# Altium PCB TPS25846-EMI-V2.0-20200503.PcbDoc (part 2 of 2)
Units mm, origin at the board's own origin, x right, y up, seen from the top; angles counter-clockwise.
Board outline 35.01 x 50.01 mm, 4 copper layers (Top Layer, Signal Layer 1, Signal Layer 2, Bottom Layer), stack 2.155 mm thick; 63 components, 30 nets, 189 pads, 82 vias.
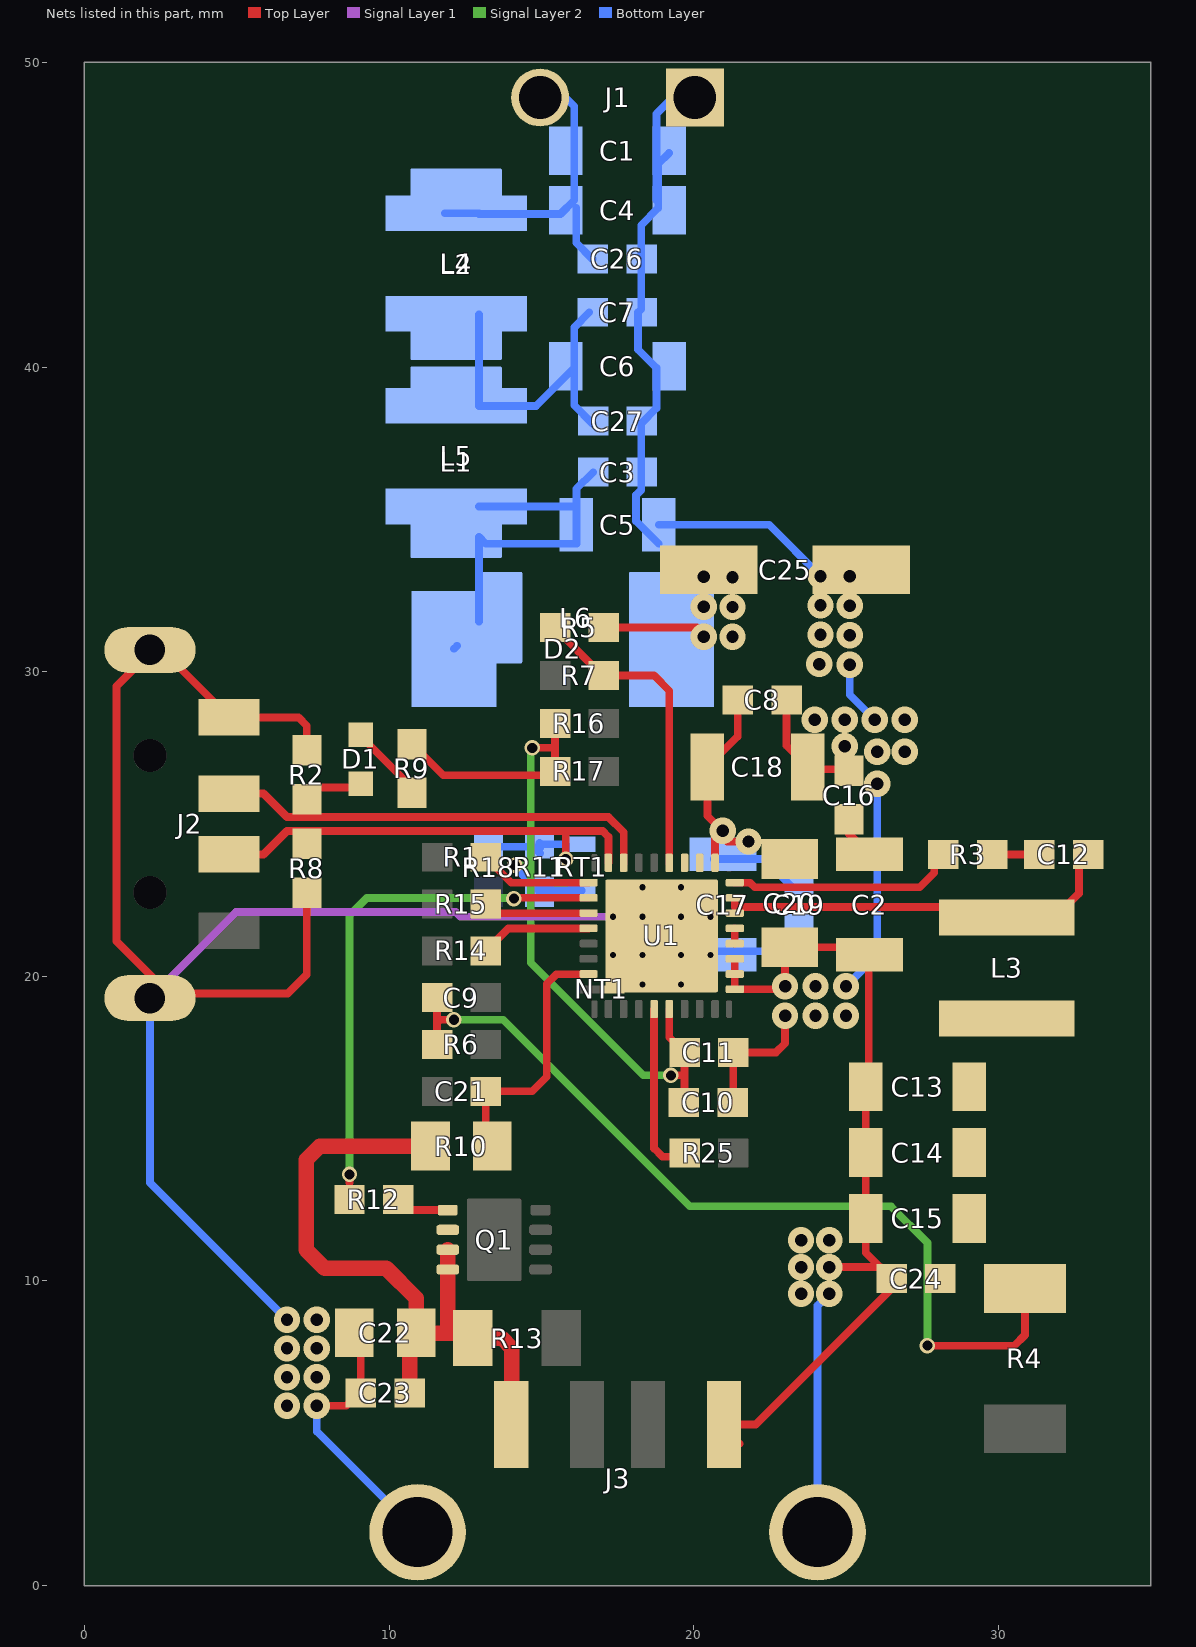
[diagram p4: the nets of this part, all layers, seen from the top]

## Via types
v1: diameter 0.864, hole 0.406, Top Layer to Bottom Layer, 56 vias
v2: diameter 0.508, hole 0.33, Top Layer to Bottom Layer, 14 vias
v3: diameter 0.5, hole 0.2, Top Layer to Bottom Layer, 12 vias

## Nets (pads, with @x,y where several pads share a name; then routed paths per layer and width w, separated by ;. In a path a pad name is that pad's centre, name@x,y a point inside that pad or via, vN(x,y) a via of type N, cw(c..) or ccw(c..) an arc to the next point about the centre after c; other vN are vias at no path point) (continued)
DATA_OUT_N: J2.2 R8.2 R11.1 R18.2 RT1.1 U1.8 | length 17.9
  Top Layer w0.254: J2.2@4.75,24 5.877,24 6.648,24.771 15.85,24.771 ; v2(15.8,23.85) 15.8,24.721 15.85,24.771 ; U1.8@17.2,23.725 17.2,24.582 17.01,24.771 15.85,24.771
  Bottom Layer w0.254: R18.2@13.239,24.25 14.74,24.25 R11.1@14.953,24.037 ; R11.1@14.915,24.25 R11.1@14.953,24.212 ; R11.1@14.94,24.375 14.978,24.337 15.8,24.337 v2(15.8,23.85)
DATA_OUT_P: D1.1 J2.3 R2.2 U1.7 | length 16.4
  Top Layer w0.254: J2.3@4.75,26 5.877,26 6.648,25.229 17.2,25.229 17.7,24.728 U1.7@17.7,23.725 U1.7@17.7,23.72 ; R2.2@7.3,25.816 7.684,26.2 D1.1@9.075,26.2
IN: C2.1 C8.1 C16.1 C17.1 C18.1 C19.1 C20.1 C25.1 D2.1 L6.2 R5.2 U1.1 U1.2 U1.3 | length 14.6
  Top Layer w0.254: R5.2@17.05,31.45 20.112,31.45 20.325,31.237 v1(20.325,31.15) ; U1.1@20.7,23.725 20.7,24.725 20.75,24.775 v1@20.85,24.675 ; v1(20.95,24.775) 20.45,25.275 C18.1@20.45,26.875 21.45,27.875 C8.1@21.45,29.075 ; v1@21.1,24.425 v1(21.8,24.425) ; C16.1@25.1,25.15 25.1,24.675 C2.1@25.775,24
  Bottom Layer w0.254: C17.1@20.659,23.85 22.3,23.85 C19.1@23.15,23
  other v1: 21.275,31.15 20.325,32.132 21.275,32.125 21.275,33.1 20.325,33.114
LS_GD: R12.1 U1.10 | length 16.9
  Top Layer w0.254: 8.7,13.225 v2(8.7,13.5) ; v2@14.055,22.575 U1.10@16.55,22.575
  Signal Layer 2 w0.254: v2(8.7,13.5) 8.7,22 9.27,22.57 v2@14.05,22.57
  other v2: 14.1,22.55
NetC3_1: C3.1 C5.1 D2.2 L1.2 L5.2 L6.1 | length 12
  Bottom Layer w0.254: D2.2@12.131,30.75 D2.2@12.231,30.85 ; D2.2@12.95,31.649 12.95,34.425 13.175,34.2 16.15,34.2 C5.1@16.15,34.825 C5.1@16.15,35.441 ; L5.2@12.95,35.424 16.133,35.424 C5.1@16.15,35.441 ; C3.1@16.7,36.55 16.15,36 C5.1@16.15,35.441
NetC6_1: C6.1 C7.1 C27.1 L1.1 L2.2 L4.2 L5.1 | length 10.7
  Bottom Layer w0.254: L4.2@12.95,41.724 12.95,40.925 12.95,39.325 12.95,38.726 14.826,38.726 C6.1@16.075,39.975 ; C7.1@16.575,41.8 16.075,41.3 C6.1@16.075,39.975 ; C27.1@16.675,38.15 16.075,38.75 C6.1@16.075,39.975
NetC9_2: C9.2 C13.1 C14.1 C15.1 C24.1 L3.2 R4.1 R6.2 | length 29.1
  Top Layer w0.254: C9.2@11.575,19.299 11.575,18.475 ; R6.2@11.662,17.849 R6.2@11.575,17.762 11.575,18.475 ; v2(12.125,18.574) 11.674,18.574 11.575,18.475 ; v2(27.675,7.875) 30.525,7.875 30.875,8.225 R4.1@30.875,9.75
  Signal Layer 2 w0.254: v2(12.125,18.574) 13.75,18.574 19.873,12.45 26.475,12.45 27.675,11.25 v2(27.675,7.875)
NetC12_1: C12.1 R3.2 | length 1.6
  Top Layer w0.254: R3.2@29.5,24 31.025,24 C12.1@31.05,24.025
NetC21_1: C21.1 R10.1 U1.15 | length 8.6
  Top Layer w0.254: R10.1@13.391,14.425 13.175,14.641 C21.1@13.175,16.225 14.7,16.225 15.175,16.7 15.175,19.75 15.495,20.07 U1.15@16.55,20.07
NetC22_1: C22.1 C23.1 J3.1 Q1.6 Q1.7 Q1.8 R10.2 R13.1 | length 23.4
  Top Layer w0.508: C23.1@10.672,6.375 10.672,8.059 C22.1@10.888,8.275 ; R10.2@11.359,14.425 7.725,14.425 7.275,13.975 7.275,11.022 7.881,10.416 9.906,10.416 10.888,9.434 C22.1@10.888,8.275 ; Q1.7@11.925,11.025 Q1.8@11.925,10.375 11.925,8.325 11.975,8.275 ; R13.1@12.71,8.385 R13.1@12.6,8.275 ; J3.1@14.01,5.285 14.025,5.3 14.025,7.8 13.7,8.125 R13.1@12.75,8.125 R13.1@12.6,8.275 ; C22.1@10.888,8.275 11.975,8.275 ; 11.975,8.275 R13.1@12.6,8.275
NetD1_2: D1.2 R9.1 | length 2.6
  Top Layer w0.254: D1.2@9.075,27.925 9.075,27.875 10.747,26.203 R9.1@10.747,26.025
NetQ1_5: Q1.5 R12.2 | length 1.7
  Top Layer w0.254: R12.2@10.3,12.525 10.5,12.325 Q1.5@11.925,12.325
NetR1_2: R1.2 U1.9 | length 3.7
  Top Layer w0.254: R1.2@13.175,23.907 14.012,23.07 U1.9@16.55,23.07
NetR3_1: R3.1 U1.32 | length 7.4
  Top Layer w0.254: U1.32@21.35,23.075 21.85,23.075 22,22.925 27.425,22.925 27.9,23.4 R3.1@27.9,24
NetR5_1: R5.1 R7.2 U1.4 | length 10.2
  Top Layer w0.254: R5.1@15.45,31.55 15.45,31.425 R7.2@16.9,29.975 ; R7.2@17.05,29.874 18.701,29.874 19.2,29.375 U1.4@19.2,23.72
NetR14_2: R14.2 U1.12 | length 3.7
  Top Layer w0.254: R14.2@13.175,20.834 13.911,21.57 U1.12@16.55,21.57
NetR15_1: R15.1 U1.11 | length 3.4
  Top Layer w0.254: R15.1@13.175,22.05 13.195,22.07 U1.11@16.55,22.07
NetR25_2: R25.2 U1.20 | length 5.7
  Top Layer w0.254: U1.20@18.7,18.92 18.7,14.35 18.975,14.075 19.575,14.075 R25.2@19.7,14.2
PGND: C1.2 C2.2 C3.2 C4.2 C5.2 C6.2 C7.2 C8.2 C10.2 C11.2 C13.2 C14.2 C15.2 C16.2 C17.2 C18.2 C19.2 C20.2 C22.2 C23.2 C24.2 C25.2 C26.2 C27.2 J1.1 J2.4 J2.5 J2.6 J3.4 J3.5 J3.6 NT1.1 R2.1 R8.1 U1.25 U1.26 U1.27 U1.33@18.95,21.325 | length 148.1
  Top Layer w0.254: J2.6@2.15,30.715 J2.6@2.24,30.715 ; R8.1@7.3,22.75 7.3,20.06 6.675,19.435 2.765,19.435 1.05,21.15 1.05,29.525 J2.6@2.24,30.715 ; R2.1@7.3,27.416 7.3,28.225 7.025,28.5 J2.4@4.75,28.5 2.535,30.715 J2.6@2.24,30.715 ; v1(7.625,5.9) 8.597,5.9 9.072,6.375 9.072,8.059 C22.2@8.856,8.275 ; U1.33@18.95,21.325 19.349,20.926 19.25,20.926 19.25,20.553 19.443,20.36 19.58,20.36 v3(19.58,19.725) ; J3.4@20.99,5.285 J3.4@21.29,5.285 ; C10.2@21.275,15.858 21.3,15.883 C11.2@21.3,17.5 22.7,17.5 23,17.8 v1(23,18.7) ; U1.27@21.35,20.575 U1.26@21.35,20.075 U1.25@21.35,19.575 22.9,19.575 v1(23,19.675) 23,20.8 C20.2@23.15,20.95 25.65,20.95 C2.2@25.75,20.85 ; J3.4@21.515,4.65 21.29,4.875 J3.4@21.29,5.285 ; C8.2@23.05,29.075 23.05,27.575 C18.2@23.75,26.875 23.675,26.8 25.05,26.8 C16.2@25.1,26.75 ; v1(24.45,10.453) C24.2@26.122,10.453 ; C2.2@25.75,20.7 25.75,16.45 25.65,16.35 C14.2@25.65,14.212 25.65,10.925 C24.2@26.122,10.453 ; J3.4@21.29,5.285 22.035,5.285 26.5,9.75 C24.2@26.5,10.075 C24.2@26.122,10.453
  Signal Layer 1 w0.254: J2.5@2.15,19.285 4.972,22.107 12.189,22.107 12.342,21.955 v3(17.35,21.955)
  Bottom Layer w0.254: J2.5@2.15,19.285 2.15,13.223 v1(6.648,8.725) ; v1(7.625,5.9) 7.625,5.06 J3.5@10.935,1.75 ; C4.2@18.775,45.475 18.775,48.31 J1.1@20.09,49.625 ; C5.2@18.85,34.2 18.109,34.941 18.109,35.8 18.275,35.966 18.275,38.15 18.775,38.65 18.775,39.975 18.175,40.575 18.175,41.8 18.275,41.9 18.275,44.66 18.84,45.225 18.84,46.675 C1.2@19.19,47.025 ; C5.2@18.85,34.825 22.476,34.825 v1(24.161,33.139) ; v3(20.55,20.695) 20.68,20.825 22.575,20.825 C19.2@23.15,21.4 ; J3.6@24.065,1.75 24.065,9.19 v1(24.45,9.575) ; v1(25,19.675) 26.025,20.7 v1(26.025,26.325) ; v1(25.125,30.225) 25.125,29.242 v1(25.942,28.425)
  other v1: 6.648,5.9 6.648,6.842 7.625,6.842 6.648,7.783 7.625,7.783 7.625,8.725 23.525,9.575 23.525,10.453 23.525,11.331 24.45,11.331 24,18.7 25,18.7 24,19.675 26.025,27.375 26.925,27.375 24.958,27.55 23.975,28.425 24.958,28.425 26.925,28.425 24.125,30.25 25.125,31.196 24.161,31.213 25.125,32.168 24.161,32.176 25.125,33.139
  other v3: 18.32,19.725 17.35,20.695 18.32,20.695 19.58,20.695 18.32,21.955 19.58,21.955 20.55,21.955 18.32,22.925 19.58,22.925
SW: C12.2 L3.1 U1.28 U1.29 U1.30 U1.31 | length 13.9
  Top Layer w0.254: U1.28@21.35,21.07 U1.28@21.35,21.075 U1.29@21.35,21.57 ; U1.31@21.35,22.57 21.35,22.275 29.855,22.275 L3.1@30.2,21.93 ; L3.1@30.275,21.93 31.86,21.93 32.65,22.72 C12.2@32.65,24.025
  Top Layer w0.508: L3.1@30.2,21.93 L3.1@30.2,22.03
VBAT: C1.1 C4.1 C26.1 J1.2 L2.1 L4.1 | length 10.9
  Bottom Layer w0.254: L4.1@11.825,45.05 L4.1@12.95,45.05 ; L4.1@12.95,45.026 15.626,45.026 16.075,45.475 16.075,48.56 J1.2@15.01,49.625 ; C4.1@16.14,45.225 16.14,44.085 C26.1@16.675,43.55
VCC: C10.1 C11.1 R9.2 R11.2 R16.2 R17.2 RT1.2 U1.21 | length 27.6
  Top Layer w0.254: R9.2@10.747,27.625 11.775,26.597 15.322,26.597 R17.2@15.45,26.725 15.45,27.5 ; v2(14.7,27.5) 15.45,27.5 ; R16.2@15.45,28.301 15.45,27.5 ; R16.2@15.675,28.301 R16.2@15.675,28.325 ; U1.21@19.2,18.92 19.2,18 C11.1@19.7,17.5 19.7,16.75 ; v2(19.25,16.75) 19.7,16.75 ; C10.1@19.675,15.858 19.7,15.883 19.7,16.75
  Signal Layer 2 w0.254: v2(14.125,23.65) 14.65,23.65 ; v2(14.7,27.5) 14.65,27.45 14.65,23.65 ; v2(19.25,16.75) 18.35,16.75 14.65,20.45 14.65,23.65
  Bottom Layer w0.254: v2(14.125,23.65) 14.125,23.59 R11.2@14.94,22.775 14.978,22.813 RT1.2@16.325,22.813 ; R11.2@14.915,22.65 R11.2@14.94,22.65
pads on no net: J2.1 J2.7 J2.8 Q1.4 Q1.9 U1.19 U1.22 U1.23 U1.33@17.69,20.065 U1.33@17.69,21.325 U1.33@17.69,22.585 U1.33@18.95,20.065 U1.33@18.95,21.325 U1.33@18.95,22.585 U1.33@20.21,20.065 U1.33@20.21,21.325 U1.33@20.21,22.585 U1.A1 U1.A2 U1.A3 U1.A4
copper on no net: | length 5.9
  Top Layer w0.254: 17.347,19.57 17.347,19.717 ; 18.32,20.69 18.32,21.95 19.58,21.95 19.58,22.92 18.32,22.92 ; 19.58,20.69 20.55,20.69

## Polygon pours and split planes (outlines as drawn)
IN on Top Layer "TOP_LAYER_IN_P204" (solid, remove dead copper, pour order 204): 18.145,34.175 21.916,34.175 22.091,34 22.091,30.241 21.825,29.975 19.625,29.975 19.2,30.4 18.1,30.4 17.9,30.6 17.9,33.964
CSN on Top Layer "TOP_LAYER_CSN_P182" (solid, remove dead copper, pour order 182): 15.5,13.6 16.64,13.6 16.75,13.49 16.75,7.065 16.635,6.95 14.925,6.95 14.775,7.1 14.775,8.94 14.525,9.19 14.525,11.85 14.65,11.975 15.29,11.975 15.415,12.1 15.415,13.475
NetC22_1 on Top Layer "TOP_LAYER_NETC22_1_P180" (solid, remove dead copper, pour order 180): 10.2,11.759 10.316,11.875 12.215,11.875 12.3,11.79 12.3,9.214 12.5,9.1 12.575,9.1 14.262,9.1 14.575,8.787 14.575,3.71 14.465,3.6 10.369,3.6 10.2,3.78 10.2,4.075
SW on Top Layer "TOP_LAYER_SW_P176" (solid, remove dead copper, pour order 176): 21.05,22.7 21.649,22.7 21.799,22.55 27.745,22.55 28.21,23.015 32.95,23.015 33.115,22.85 33.115,20.915 32.987,20.787 28.388,20.787 27.675,21.5 24.625,21.5 24.275,21.85 22.075,21.85 21.9,21.675 21.9,21.1 21.734,20.934 21.05,20.934
IN on Top Layer "TOP_LAYER_IN_P174" (solid, remove dead copper, pour order 174): 19.806,33.85 21.887,33.85 22.091,33.645 22.091,25.984 22.55,25.525 26.7,25.525 26.95,25.275 26.95,23.409 26.666,23.125 22.25,23.125 21.3,24.075 21.275,24.1 21.05,24.1 20.965,24.015 20.965,23.465 20.895,23.395 19.619,23.395 19.619,33.605
no net on Top Layer "TOP_LAYER_NONET_P172" (solid, remove dead copper, pour order 172): 19.434,33.8
PGND on Top Layer "TOP_LAYER_PGND_P170" (solid, remove dead copper, pour order 170): 20.15,20.775 20.235,20.69 21.01,20.69 21.025,20.675 21.025,20.364 20.79,20.129 20.62,20.3 20.2,20.3 20.2,20.65 20.15,20.7
PGND on Top Layer "TOP_LAYER_PGND_P158" (solid, remove dead copper, pour order 158): 1.575,34.125 33.327,34.125 34.15,33.302 34.15,1.133 33.525,0.508 1.425,0.508 0.7,1.233 0.7,33.25
no net on Top Layer "TOP_LAYER_NONET_P156" (solid, remove dead copper, pour order 156): 1.225,33.775
CSN on Top Layer "TOP_LAYER_CSN_P152" (solid, remove dead copper, pour order 152): 26.825,6.475 32.375,6.475 32.745,6.105 32.745,4.295 32.4,3.95 26.85,3.95 26.475,4.325 26.475,6.125
NetC9_2 on Top Layer "TOP_LAYER_NETC9_2_P150" (solid, remove dead copper, pour order 150): 27.575,19.153 28.102,19.525 32.275,19.525 32.6,19.2 32.6,8.95 32.075,8.425 27.971,8.425 27.575,8.98
no net on Top Layer "TOP_LAYER_NONET_P132" (solid, remove dead copper, pour order 132): 21.525,24.872
no net on Top Solder "TOP_LAYER_NONET_P-001" (solid, remove dead copper): -35.968,-41.976
PGND on Signal Layer 2 "SIGNAL_LAYER_2_PGND_P188" (solid, remove dead copper, pour order 188): 1.525,34.175 33.187,34.175 34.1,33.262 34.1,1.183 33.475,0.558 1.375,0.558 0.65,1.283 0.65,33.3
CSN on Signal Layer 2 "SIGNAL_LAYER_2_CSN_P184" (solid, remove dead copper, pour order 184): 14.05,13.7 16.54,13.7 16.9,13.34 16.9,10.825 21.375,6.35 29.625,6.35 29.95,6.025 29.95,4 29.625,3.675 20,3.675 15.15,8.525 13.825,9.85 13.825,13.475
PGND on Signal Layer 1 "SIGNAL_LAYER_1_PGND_P186" (solid, remove dead copper, pour order 186): 1.575,34.125 33.327,34.125 34.15,33.302 34.15,1.133 33.525,0.508 1.425,0.508 0.7,1.233 0.7,33.25
PGND on Bottom Layer "BOTTOM_LAYER_PGND_P202" (solid, remove dead copper, pour order 202): 18.034,49.484 21.991,49.484 22.275,49.2 22.275,38.25 26.775,33.75 29.5,31.025 29.5,30.6 28.325,29.425 23.418,29.425 22.95,29.893 22.95,33.518 22.518,33.95 18.05,33.95 17.75,34.25 17.75,49.2
IN on Bottom Layer "BOTTOM_LAYER_IN_P200" (solid, remove dead copper, pour order 200): 17.85,33.425 18.075,33.65 22.45,33.65 22.625,33.475 22.625,24.425 23.3,23.75 23.8,23.75 24.065,23.485 24.065,22.64 23.825,22.4 20.8,22.4 17.85,25.35
NetC3_1 on Bottom Layer "BOTTOM_LAYER_NETC3_1_P196" (solid, remove dead copper, pour order 196): 9.35,37.1 17.15,37.1 17.3,36.95 17.3,28.775 17.1,28.575 9.525,28.575 9.2,28.9 9.2,36.675 9.2,36.95
NetC6_1 on Bottom Layer "BOTTOM_LAYER_NETC6_1_P194" (solid, remove dead copper, pour order 194): 9.418,42.45 17.175,42.45 17.35,42.275 17.35,37.825 17.15,37.625 9.45,37.625 9.225,37.85 9.225,42.139
VBAT on Bottom Layer "BOTTOM_LAYER_VBAT_P192" (solid, remove dead copper, pour order 192): 9.829,49.825 16.525,49.825 17.3,49.05 17.3,43.1 17.075,42.875 9.5,42.875 9.225,43.15 9.225,49.267
PGND on Bottom Layer "BOTTOM_LAYER_PGND_P190" (solid, remove dead copper, pour order 190): 1.45,32.625 33.15,32.625 34.15,31.625 34.15,1.133 33.525,0.508 1.425,0.508 0.7,1.233 0.7,31.875

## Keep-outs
Keep-Out Layer:
  text ".Layer_Name" at -65.219,-64.806 h1.52

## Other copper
Top Layer:
  pour cut-out: 32.865,19.181 32.884,20.725 32.605,20.725 32.614,19.181
  pour cut-out: 27.588,19.4 27.609,21.05 27.322,21.05 27.332,19.4
  pour cut-out: 3.726,24.467 3.737,25.325 3.496,25.325 3.501,24.467
  pour cut-out: 8.695,26.671 8.705,27.529 8.464,27.529 8.47,26.671
  pour cut-out: 27.419,6.888 27.44,8.563 27.145,8.562 27.155,6.888
  pour cut-out: 32.831,5.625 32.87,8.694 32.642,8.694 32.66,5.625
  pour cut-out: 14.648,3.45 19.314,3.45 19.314,3.725 14.648,3.725
  pour cut-out: 18.088,13.467 18.946,13.456 18.946,13.698 18.088,13.692
  text ".Layer_Name" at -65.219,-64.806 h1.52
Signal Layer 2:
  pour cut-out: -4.107,-15.263
  pour cut-out: -32.098,-20.595
Bottom Layer:
  pour cut-out: -39.667,-5.687
  text ".Layer_Name" at -65.219,-64.806 h1.52

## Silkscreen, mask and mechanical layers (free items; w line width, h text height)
Top Overlay:
  pour cut-out: -60.476,-31.557
  pour cut-out: -65.87,-32.475
  lines w0.127: -79.675,-35.025 -79.45,-35.25
  text "TPS25846-EMI" at 2.175,36.65 h2 r90
  text "PMP40725" at 32.925,35.775 h2.79 r90
  text ".Layer_Name" at -65.219,-64.806 h1.52
Bottom Overlay:
  text "VIN" at 12.65,48.024 h1.85
  text "GND" at 25.225,48.025 h1.85
  text ".Layer_Name" at -65.219,-64.806 h1.52
Top Paste:
  text ".Layer_Name" at -65.219,-64.806 h1.52
Bottom Paste:
  text ".Layer_Name" at -65.219,-64.806 h1.52
Top Solder:
  rectangle: 12.988,7.15 14.487,9.1
  text ".Layer_Name" at -65.219,-64.806 h1.52
  text ".Layer_Name" at -65.219,-64.806 h1.52
Bottom Solder:
  rectangle: 14.375,30.225 17.5,33.325
  region: 21.225,46.975 21.225,49.875 18.55,49.875 18.55,46.975
  region: 16.375,47.125 16.375,49.875 13.725,49.875 13.725,47.125
  text ".Layer_Name" at -65.219,-64.806 h1.52
Drill Guide:
  text ".Layer_Name" at -65.219,-64.806 h1.52
M1 Board Outline:
  lines w0.01: -39.75,-28.25 -39.725,-28.275 ; 0,0 35,0 35,50 0,50 0,0
  lines w0.254: -82.758,-41.522 -82.25,-43.046 ; -82.758,-14.57 -82.25,-13.046 ; -82.504,-43.046 -81.996,-43.046 ; -82.504,-13.046 -81.996,-13.046 ; -82.25,-33.15 -82.25,-43.046 ; -82.25,-22.942 -82.25,-13.046 ; -81.742,-41.522 -82.25,-43.046 ; -81.742,-14.57 -82.25,-13.046 ; -79.476,-44.69 -79.476,-44.182 ; -77.952,-44.944 -79.476,-44.436 ; -77.952,-43.928 -79.476,-44.436 ; -62.08,-44.436 -79.476,-44.436 ; -51.872,-44.436 -34.476,-44.436 ; -36,-44.944 -34.476,-44.436 ; -36,-43.928 -34.476,-44.436 ; -34.476,-44.69 -34.476,-44.182
  text "30 (mm)" at -81.336,-32.896 h1.52 r90
  text "45 (mm)" at -61.826,-45.35 h1.52
  text ".Layer_Name" at -65.219,-64.806 h1.52
M2 Board Dimensions:
  rectangle: -79.875,-49.985 -76.7,-46.81
  rectangle: -76.7,-53.16 -67.175,-49.985
  lines w0.01: -80.131,-41.674 -80.098,-41.706
  lines w0.178: -79.875,-49.985 -54.475,-49.985 ; -76.7,-53.16 -76.7,-46.81 ; -73.525,-53.16 -73.525,-46.81 ; -67.175,-53.16 -67.175,-46.81 ; -60.825,-53.16 -60.825,-46.81 ; -79.875,-53.16 -54.475,-53.16 -54.475,-46.81 -79.875,-46.81 -79.875,-53.16
  text ".Layer_Name" at -65.219,-64.806 h1.52
M3 3D STEP Top:
  text ".Layer_Name" at -65.219,-64.806 h1.52
M4 3D STEP Bottom:
  text ".Layer_Name" at -65.219,-64.806 h1.52
M5 Assembly Top:
  lines w0.254: -87.292,-66.626 80.348,-66.626 ; -87.292,-61.462 80.399,-61.462 ; -87.292,-56.297 -87.292,-71.791 14.435,-71.791 80.399,-71.791 80.399,-56.297 -87.279,-56.297 -87.279,-71.791 -47.261,-71.791 ; -24.681,-71.791 -24.681,-56.297 ; 7.501,-61.462 7.501,-56.297 ; 28.837,-61.462 28.837,-56.297 ; 44.636,-71.956 44.636,-66.804
  text "COMPONENTS MARKED 'DNP' SHOULD NOT BE POPULATED." at -50.576,-51.09 h1.52
  text "ASSEMBLY VARIANT:" at -50.589,-54.024 h1.52
  text ".VariantName" at -24.274,-54.024 h1.52
  text "PCB VIEWED FROM TOP SIDE" at -85.679,-59.654 h1.52
  text "BOARD #:" at -22.776,-59.654 h1.52
  text ".PRJ_Number" at -8.92,-59.654 h1.52
  text "REV:" at 12.53,-59.654 h1.52
  text ".PCB_Rev" at 19.934,-59.654 h1.52
  text "SVN REV:" at 33.815,-59.654 h1.52
  text ".VersionControl_RevNumber" at 46.668,-59.654 h1.52
  text "TID #:" at -22.776,-64.819 h1.52
  text ".TID" at -8.92,-64.819 h1.52
  text "PLOT NAME =" at -85.679,-70.034 h1.52
  text ".plot_File_Name" at -65.219,-70.034 h1.52
  text "GENERATED    :" at -22.725,-70.034 h1.52
  text ".Print_Date" at -0.64,-70.034 h1.52
  text ".Print_Time" at 17.877,-70.034 h1.52
  text "TEXAS INSTRUMENTS" at 49.995,-70.034 h1.52
M6 Assembly Bottom:
  lines w0.254: -87.304,-61.474 80.386,-61.474 ; -87.254,-66.639 80.386,-66.639 ; -51.541,-71.969 -51.541,-66.817 ; -35.742,-61.474 -35.742,-56.31 ; -14.406,-61.474 -14.406,-56.31 ; 17.775,-71.804 17.775,-56.31 ; 40.356,-71.804 80.374,-71.804 80.374,-56.31 -87.304,-56.31 -87.304,-71.804 -21.341,-71.804 80.386,-71.804 80.386,-56.31
  text "COMPONENTS MARKED 'DNP' SHOULD NOT BE POPULATED." at 75.116,-51.077 h1.52
  text ".VariantName" at 48.598,-54.024 h1.52
  text "ASSEMBLY VARIANT:" at 74.989,-54.024 h1.52
  text ".VersionControl_RevNumber" at -53.573,-59.667 h1.52
  text "SVN REV:" at -40.721,-59.667 h1.52
  text ".PCB_Rev" at -26.84,-59.667 h1.52
  text "REV:" at -19.436,-59.667 h1.52
  text ".PRJ_Number" at 2.015,-59.667 h1.52
  text "BOARD #:" at 15.87,-59.667 h1.52
  text "PCB VIEWED FROM BOTTOM SIDE" at 78.773,-59.667 h1.52
  text ".TID" at 2.015,-64.831 h1.52
  text "TID #:" at 15.87,-64.831 h1.52
  text "TEXAS INSTRUMENTS" at -56.901,-70.047 h1.52
  text ".Print_Time" at -24.782,-70.047 h1.52
  text ".Print_Date" at -6.266,-70.047 h1.52
  text "GENERATED    :" at 15.82,-70.047 h1.52
  text ".plot_File_Name" at 58.314,-70.047 h1.52
  text "PLOT NAME =" at 78.773,-70.047 h1.52
M9 Title Sheet:
  drawing of 57 lines, arcs and shapes, not listed
  text "1" at -61.083,161.127 h1.78
  text "2" at 2.307,161.127 h1.78
  text "3" at 65.536,161.127 h1.78
  text "4" at 129.205,161.127 h1.78
  text "5" at 192.68,161.127 h1.78
  text "6" at 256.307,161.127 h1.78
  text "A" at -90.454,132.095 h1.78
  text "A" at 285.466,132.095 h1.78
  text "B" at -90.454,71.643 h1.78
  text "B" at 285.466,71.643 h1.78
  text "C" at -90.454,11.318 h1.78
  text "C" at 285.466,11.318 h1.78
  text "PROJECT TITLE:" at 208.25,-35.952 h1.14
  text ".PRJ_Title" at 209.52,-39.338 h1.78
  text "DESIGNED FOR:" at 208.25,-43.597 h1.14
  text ".PRJ_Customer" at 209.52,-47.153 h1.78
  text "D" at -90.454,-48.88 h1.78
  text "D" at 285.466,-48.88 h1.78
  text "FILE NAME:" at 208.25,-51.217 h1.14
  text ".PCB_File_Name_No_Path" at 209.52,-54.265 h1.78
  text "Texas Instruments (TI) and/or its licensors do not warrant the accuracy or completeness of this specification" at 82.025,-58.376 h1.14
  text "ENGINEER:" at 208.25,-58.583 h1.14
  text "LAYOUT BY:" at 246.477,-58.583 h1.14
  text "or any information contained therein. TI and/or its licensors do not warrant that this design will meet" at 80.882,-61.237 h1.14
  text ".PRJ_Engineer" at 209.52,-62.52 h1.78
  text ".PCB_Layout" at 247.76,-62.52 h1.78
  text "the specifications, will be suitable for your application or fit for any particular purpose, or will operate in" at 80.882,-64.099 h1.14
  text ".Layer_Name" at -65.219,-64.806 h1.52
  text "ALTIUM DESIGNER VERSION:" at 246.477,-66.457 h1.14
  text "an implementation. TI and/or its licensors do not warrant that the design is production worthy. You should" at 80.882,-66.961 h1.14
  text "completely validate and test your design implementation to confirm the system functionality for your application." at 82.025,-69.822 h1.14
  text ".print_Scale" at 209.52,-69.843 h1.78
  text ".Application_BuildNumber" at 247.76,-69.843 h1.78
  text "1" at -61.083,-75.093 h1.78
  text "2" at 2.307,-75.093 h1.78
  text "3" at 65.536,-75.093 h1.78
  text "4" at 129.205,-75.093 h1.78
  text "5" at 192.68,-75.093 h1.78
  text "6" at 256.307,-75.093 h1.78
M10 Fab Notes:
  drawing of 189 lines, arcs and shapes, not listed
  text "DESIGN INFORMATION" at 234.628,118.447 h1.52
  text "MIN. TRACK WIDTH:" at 218.256,115.091 h1.52
  text "8" at 246.101,115.091 h1.52
  text "MIL" at 250.032,115.091 h1.52
  text "MIN. CLEARANCE:" at 218.256,111.938 h1.52
  text "0.2" at 244.577,111.938 h1.52
  text "mm" at 250.032,111.938 h1.52
  text "MIN. VIA PAD SIZE:" at 218.256,108.785 h1.52
  text "24" at 245.339,108.785 h1.52
  text "MIL" at 250.032,108.785 h1.52
  text "0.05mm (2MIL)" at 235.909,105.486 h1.52
  text "MINIMUM ANNULAR RING" at 209.894,105.277 h1.52
  text "EXTERNAL" at 253.893,105.277 h1.52
  text "PER" at 214.974,102.48 h1.52
  text "IPC-D-275 CLASS 2 LEVEL C" at 220.562,102.48 h1.52
  text "MIL, HOLES" at 258.363,99.928 h1.52
  text "+/-" at 248.395,99.709 h1.52
  text "+/-" at 270.086,99.709 h1.52
  text "REGISTRATION TOLERANCES:" at 209.894,99.682 h1.52
  text "METAL" at 240.368,99.682 h1.52
  text "5" at 255.004,99.683 h1.52
  text "3" at 276.162,99.683 h1.52
  text "MIL" at 279.115,99.682 h1.52
  text "HOLE SIZE TOLERANCE (UNLESS OTHERWISE SPECIFIED):" at 209.894,97.185 h1.52
  text "+/-" at 270.086,97.112 h1.52
  text "3" at 276.162,97.085 h1.52
  text "MIL" at 279.115,97.085 h1.52
  text "MATERIAL:" at 207.995,93.589 h1.52
  text "FR-4 High Tg" at 233.051,90.324 h1.52
  text "X" at 229.382,90.122 h1.52
  text "FR-408" at 218.688,90.007 h1.52
  text "OTHER" at 256.483,90.007 h1.52
  text "62 MIL (1.6mm) +/-10%" at 226.819,86.374 h1.52
  text "X" at 223.768,86.312 h1.52
  text "THICKNESS:" at 209.894,86.165 h1.52
  text "OTHER" at 259.455,86.165 h1.52
  text "TOLERANCE:" at 209.894,82.652 h1.52
  text "X" at 231.439,82.652 h1.52
  text "ANSI IPC-6012 TYPE 3 CLASS 2" at 235.961,82.652 h1.52
  text "OTHER +/-" at 235.96,78.989 h1.52
  text "BOW & TWIST:" at 209.894,75.302 h1.52
  text "X" at 231.439,75.302 h1.52
  text "ANSI IPC-6012 TYPE 3 CLASS 2" at 235.961,75.302 h1.52
  text "OTHER +/-" at 235.96,71.576 h1.52
  text "DRILLING:" at 207.995,68.258 h1.52
  text "NC_DRILL FILES" at 252.724,65.586 h1.52
  text "REFERENCE:" at 209.894,65.486 h1.52
  text "X" at 226.588,65.484 h1.52
  text "AS SHOWN" at 231.109,65.486 h1.52
  text "X" at 249.473,65.486 h1.52
  text "OTHER" at 260.293,61.873 h1.52
  text "PTH COPPER THICKNESS:" at 209.886,61.783 h1.52
  text "X" at 238.822,61.783 h1.52
  text "20-30 um" at 242.073,61.783 h1.52
  text "BOARD FINISH:" at 207.995,58.034 h1.52
  text "SILKSCREEN:" at 211.938,55.237 h1.52
  text "X" at 236.265,55.237 h1.52
  text "TOP" at 239.237,55.237 h1.52
  text "X" at 249.219,55.237 h1.52
  text "BOTTOM" at 252.216,55.237 h1.52
  text "SILKSCREEN COLOR:" at 211.938,51.295 h1.52
  text "X" at 236.24,51.295 h1.52
  text "WHITE" at 239.237,51.295 h1.52
  text "OTHER" at 252.216,51.295 h1.52
  text "X" at 239.567,47.652 h1.52
  text "GREEN" at 242.564,47.652 h1.52
  text "OTHER" at 258.261,47.652 h1.52
  text "SOLDER RESIST COLOR:" at 211.938,47.477 h1.52
  text "X" at 239.567,43.734 h1.52
  text "MATTE" at 242.564,43.734 h1.52
  text "SEMI-GLOSS" at 258.25,43.717 h1.52
  text "IMMERSION GOLD (ENIG)" at 234.944,39.345 h1.52
  text "ENEPIG" at 268.918,39.162 h1.52
  text "SURFACE FINISH:" at 207.995,39.136 h1.52
  text "X" at 230.423,39.136 h1.52
  text "IMM. TIN/SILVER OR EQUIV" at 216.365,35.649 h1.52
  text "OTHER" at 252.724,35.549 h1.52
  text "ARRAY/PANEL:" at 207.995,31.602 h1.52
  text "CUT AND TRIM PER M1 BOARD OUTLINE" at 234.944,31.393 h1.52
  text "N.C. ROUTE" at 234.944,27.94 h1.52
  text "X" at 252.42,27.94 h1.52
  text "V. SCORE" at 256.941,27.94 h1.52
  text "CERTIFICATION:" at 207.995,24.66 h1.52
  text "MATERIALS AND WORKMANSHIP FOR ALL PCBS" at 226.41,24.66 h1.52
  text "TO MEET OR EXCEED THE REQUIREMENTS OF:" at 226.41,22.271 h1.52
  text "X" at 217.203,19.003 h1.52
  text "ANSI IPC-A-600F CLASS ->" at 220.454,19.003 h1.52
  text "X" at 262.313,19.003 h1.52
  text "2" at 265.107,19.003 h1.52
  text "1" at 257.106,18.965 h1.52
  text "3" at 274.098,18.965 h1.52
  text "X" at 237.827,15.252 h1.52
  text "RoHS" at 241.078,15.252 h1.52
  text "OTHER" at 257.446,15.252 h1.52
  text "PER ORDER" at 267.532,15.252 h1.52
  text "ALL BOARDS MUST MEET OR EXCEED UL94-V0 REQUIREMENTS." at 208.694,11.345 h1.52
  text "PCB MUST BEAR THE UL94V-0 UL REGISTERED MATERIAL ID NUMBER" at 208.694,8.397 h1.52
  text "ADDITIONAL REQUIREMENTS:" at 207.995,4.094 h1.52
  text "MICROSECTION:" at 209.894,1.373 h1.52
  text "YES" at 232.9,1.373 h1.52
  text "REQUIRED" at 254.782,-2.293 h1.52
  text "BARE BOARD ELEC. TEST:" at 209.894,-2.366 h1.52
  text "NONE" at 243.06,-2.366 h1.52
  text "X" at 251.785,-2.366 h1.52
  text "PER ORDER" at 269.818,-2.366 h1.52
  text "XX MIL VIAS REQUIRE NON-CONDUCTIVE FILL AND PLANARIZE" at 214.165,-7.572 h1.5
  text "XX MIL VIAS REQUIRE CONDUCTIVE FILL AND PLANARIZE" at 214.368,-10.213 h1.52
  text "OUTER XX MIL TRACES REQUIRE 50 OHM SINGLE-ENDED IMPEDANCE" at 214.343,-14.363 h1.47
  text "LAYER 2 & 3 (INNER LAYERS) XX MIL WIDE, XX MIL SPACE / TRACES REQUIRE 100 OHM DIFFERENTIAL IMPEDANCE" at 214.14,-20.35 h1.52
  text ".Layer_Name" at -65.219,-64.806 h1.52
M11 Gerber Information:
  lines w0.254: -87.292,-66.626 80.348,-66.626 ; -87.292,-61.462 80.399,-61.462 ; -87.292,-56.297 -87.292,-71.791 14.435,-71.791 80.399,-71.791 80.399,-56.297 -87.279,-56.297 -87.279,-71.791 -47.261,-71.791 ; -24.681,-71.791 -24.681,-56.297 ; 7.501,-61.462 7.501,-56.297 ; 28.837,-61.462 28.837,-56.297 ; 44.636,-71.956 44.636,-66.804
  text "ALL ARTWORK VIEWED FROM TOP SIDE" at -85.679,-59.654 h1.52
  text "BOARD #:" at -22.776,-59.654 h1.52
  text ".PRJ_Number" at -8.92,-59.654 h1.52
  text "REV:" at 12.53,-59.654 h1.52
  text ".PCB_Rev" at 19.934,-59.654 h1.52
  text "SVN REV:" at 33.815,-59.654 h1.52
  text ".VersionControl_RevNumber" at 46.668,-59.654 h1.52
  text "LAYER NAME =" at -85.679,-64.806 h1.52
  text "TID #:" at -22.776,-64.819 h1.52
  text ".TID" at -8.92,-64.819 h1.52
  text "PLOT NAME =" at -85.679,-70.034 h1.52
  text ".plot_File_Name" at -65.219,-70.034 h1.52
  text "GENERATED    :" at -22.725,-70.034 h1.52
  text ".Print_Date" at -0.64,-70.034 h1.52
  text ".Print_Time" at 17.877,-70.034 h1.52
  text "TEXAS INSTRUMENTS" at 49.995,-70.034 h1.52
M12 Stackup:
  drawing of 295 lines, arcs and shapes, not listed
  text "Layer" at 169.34,128.448 h1.52
  text "Name" at 179.751,128.448 h1.52
  text "Material" at 203.621,128.448 h1.52
  text "Thickness" at 225.459,128.448 h1.52
  text "Constant" at 241.965,128.448 h1.52
  text "Board Layer Stack" at 256.439,128.448 h1.52
  text "1" at 169.34,125.4 h1.52
  text "Top Overlay" at 179.751,125.4 h1.52
  text "2" at 169.34,122.352 h1.52
  text "Top Solder" at 179.751,122.352 h1.52
  text "Solder Resist" at 203.621,122.352 h1.52
  text "0.40mil" at 225.459,122.352 h1.52
  text "3.5" at 241.965,122.352 h1.52
  text "3" at 169.34,119.304 h1.52
  text "Top Layer" at 179.751,119.304 h1.52
  text "Copper" at 203.621,119.304 h1.52
  text "1.40mil" at 225.459,119.304 h1.52
  text "4" at 169.34,116.256 h1.52
  text "Dielectric1" at 179.751,116.256 h1.52
  text "FR-4" at 203.621,116.256 h1.52
  text "59.20mil" at 225.459,116.256 h1.52
  text "4.8" at 241.965,116.256 h1.52
  text "5" at 169.34,113.208 h1.52
  text "Signal Layer 1" at 179.751,113.208 h1.52
  text "Copper" at 203.621,113.208 h1.52
  text "1.42mil" at 225.459,113.208 h1.52
  text "6" at 169.34,110.16 h1.52
  text "Dielectric 2" at 179.751,110.16 h1.52
  text "10.00mil" at 225.459,110.16 h1.52
  text "4.2" at 241.965,110.16 h1.52
  text "7" at 169.34,107.112 h1.52
  text "Signal Layer 2" at 179.751,107.112 h1.52
  text "Copper" at 203.621,107.112 h1.52
  text "1.42mil" at 225.459,107.112 h1.52
  text "8" at 169.34,104.064 h1.52
  text "Dielectric 3" at 179.751,104.064 h1.52
  text "10.00mil" at 225.459,104.064 h1.52
  text "4.2" at 241.965,104.064 h1.52
  text "9" at 169.34,101.016 h1.52
  text "Bottom Layer" at 179.751,101.016 h1.52
  text "Copper" at 203.621,101.016 h1.52
  text "1.40mil" at 225.459,101.016 h1.52
  text "10" at 169.34,97.968 h1.52
  text "Bottom Solder" at 179.751,97.968 h1.52
  text "Solder Resist" at 203.621,97.968 h1.52
  text "0.40mil" at 225.459,97.968 h1.52
  text "3.5" at 241.965,97.968 h1.52
  text "11" at 169.34,94.92 h1.52
  text "Bottom Overlay" at 179.751,94.92 h1.52
  text ".Layer_Name" at -65.219,-64.806 h1.52
M13 Component Bodies Top:
  text ".Layer_Name" at -65.219,-64.806 h1.52
M14 Component Bodies Bottom:
  text ".Layer_Name" at -65.219,-64.806 h1.52
M15 Courtyards Top:
  text ".Layer_Name" at -65.219,-64.806 h1.52
M16 Courtyards Bottom:
  text ".Layer_Name" at -65.219,-64.806 h1.52
Drill Drawing:
  text ".Layer_Name" at -65.219,-64.806 h1.52
M17 Embedded Cavity:
  text ".Layer_Name" at -65.219,-64.806 h1.52
M18 Embedded Assembly:
  text ".Layer_Name" at -65.219,-64.806 h1.52
M19 Embedded Keepout:
  text ".Layer_Name" at -65.219,-64.806 h1.52

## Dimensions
-79.875,-53.16 to -54.475,-53.16 on M2 Board Dimensions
